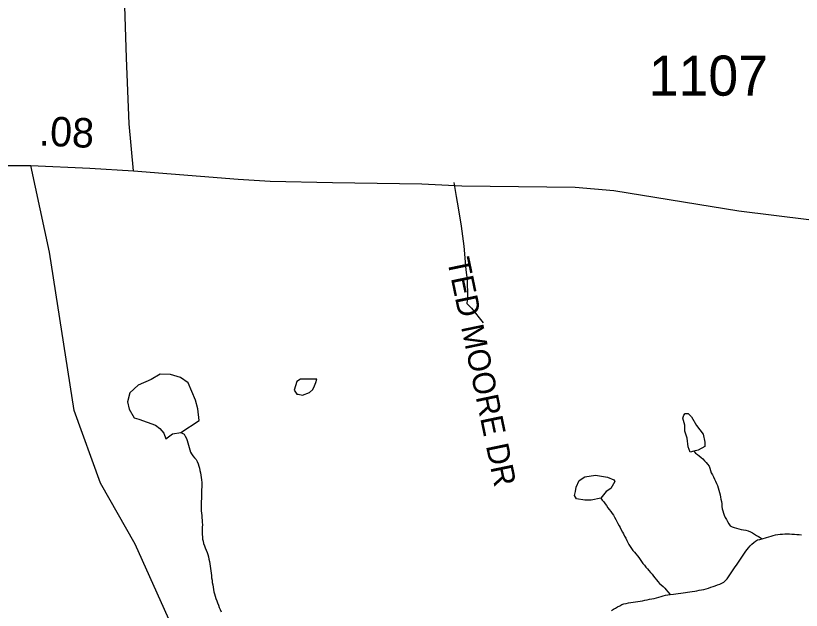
# Model space of a CAD drawing. Extents: x 1950930 to 2061844, y 904556 to 1017002.
# Drawn here: x 1975648 to 1978977, y 917429 to 919951 of the extents above; entities that cross this region are included whole.
import ezdxf

# ---------------------------------------------------------------- set-up
doc = ezdxf.new("R2010")
doc.units = 0
for name, color, linetype in [('Exist Hydrographic Creek Single Shore', 7, 'Continuous'), ('Exist Hydrographic Misc Water Feature', 7, 'Continuous'), ('Exist Road Non-System Type 51', 7, 'Continuous'), ('Exist Road Non-System Type 51 Label', 7, 'Continuous'), ('Exist Road Primary US Structure Standard Bridge CELL', 7, 'Continuous'), ('Exist Road Secondary Type 51 Attributed', 7, 'Continuous'), ('Exist Road Secondary Type 51 Number Label', 7, 'Continuous')]:
    doc.layers.add(name, color=color, linetype=linetype)

msp = doc.modelspace()

# ---------------------------------------------------------------- linework, layer by layer
at = {"layer": 'Exist Hydrographic Creek Single Shore'}
for points in [[(1978811.5, 917731.8), (1978830.3, 917737.1), (1978839.8, 917740.1), (1978849.2, 917743.1), (1978858.4, 917745.8), (1978868.3, 917748.7), (1978878.3, 917750.1), (1978888.3, 917751.3), (1978897.8, 917751.9), (1978908, 917752.8), (1978917.9, 917752.5), (1978927.7, 917753), (1978937.8, 917751.9), (1978947.8, 917752), (1978957.9, 917750.9), (1978967.9, 917749.8), (1978978, 917748.6)], [(1978421.4, 917495.2), (1978436.4, 917497.4), (1978445.8, 917498.8), (1978455.9, 917500.1), (1978466.4, 917501.8), (1978476, 917503.2), (1978486, 917504.5), (1978495.5, 917505.9), (1978505.5, 917507.6), (1978515.2, 917509), (1978525.6, 917510.3), (1978535.2, 917511.6), (1978544.9, 917514.2), (1978554.9, 917515.5), (1978564.6, 917517.7), (1978574.4, 917519.9), (1978583.8, 917522.9), (1978593.7, 917526.3), (1978603.1, 917529.3), (1978612.6, 917532.3), (1978622.2, 917536.2), (1978631.6, 917539.2), (1978640.9, 917544.3), (1978648.8, 917548.7), (1978656.2, 917555.3), (1978662.6, 917562.4), (1978668.7, 917571.3), (1978674.3, 917579.4), (1978680, 917588.2), (1978685.8, 917596.3), (1978691.3, 917604.8), (1978696.8, 917612.9), (1978702.4, 917620.5), (1978708.1, 917629.4), (1978713.8, 917637.9), (1978719.4, 917645.9), (1978725.1, 917654), (1978730.9, 917662.9), (1978736.4, 917670.9), (1978742.4, 917679), (1978748.3, 917687), (1978754.2, 917694.2), (1978761.2, 917702.5), (1978768.2, 917709.6), (1978776, 917717), (1978783.2, 917722.7), (1978791.6, 917727.1), (1978801.8, 917729.6), (1978811.5, 917731.8)], [(1978173.1, 917427.5), (1978181.7, 917433.1), (1978190.6, 917437.8), (1978198.6, 917443.1), (1978207.6, 917448.2), (1978216.4, 917453), (1978225.8, 917456), (1978235.7, 917458.2), (1978245.3, 917460.3), (1978255.4, 917461.7), (1978264.8, 917463.1), (1978275.2, 917464.7), (1978284.9, 917466.1), (1978294.9, 917467.4), (1978305, 917468.7), (1978314.6, 917471.3), (1978324.5, 917473.5), (1978333.7, 917475.7), (1978343.7, 917477.5), (1978353.4, 917479.6), (1978363.2, 917481.8), (1978373.5, 917484.7), (1978382.9, 917487.7), (1978392.1, 917490.4), (1978401.6, 917493.3), (1978411.6, 917494.7), (1978421.4, 917495.2)]]:
    msp.add_lwpolyline(points, dxfattribs=at)
at = {"layer": 'Exist Hydrographic Misc Water Feature'}
for points in [[(1976348.4, 918182.6), (1976426.3, 918233.7), (1976419.5, 918283.4), (1976409.5, 918319.5), (1976378.9, 918393.1), (1976346.7, 918416.7), (1976304.5, 918429.2), (1976260.6, 918430.9), (1976222.9, 918407.9), (1976166.9, 918383.6), (1976131.4, 918351.6), (1976121.6, 918313.3), (1976129.6, 918281.7), (1976150.3, 918245.3), (1976170.2, 918239.8), (1976240.3, 918214.1), (1976258.4, 918200.4), (1976276.6, 918180.2), (1976284.6, 918156.3), (1976312.7, 918177.1), (1976348.4, 918182.6)], [(1976845, 918344.9), (1976863.3, 918341.3), (1976893.2, 918353), (1976907.1, 918365.1), (1976914.9, 918381.4), (1976920.5, 918395.2), (1976924.6, 918409.5), (1976910.6, 918409.2), (1976896.7, 918409.3), (1976874.9, 918409), (1976854.4, 918408.8), (1976838.9, 918399.1), (1976828.8, 918362.5), (1976839.1, 918345), (1976845, 918344.9)], [(1978522.5, 918103.7), (1978507, 918099.2), (1978498.3, 918121.5), (1978494.2, 918159), (1978484, 918189.1), (1978483.8, 918213.4), (1978475.6, 918243.1), (1978479.3, 918257.2), (1978485.4, 918263.5), (1978497.3, 918263.3), (1978511.7, 918249.8), (1978533.6, 918213.2), (1978561.7, 918175.6), (1978568.5, 918142.1), (1978568.3, 918123.9), (1978540.6, 918107.4), (1978522.5, 918103.7)], [(1976348.4, 918182.6), (1976362.3, 918176.1), (1976367, 918166.8), (1976371.9, 918157.9), (1976375, 918148.6), (1976378.1, 918138.7), (1976380.8, 918129), (1976382.8, 918119), (1976385.7, 918110), (1976388.6, 918099.8), (1976393.3, 918091.8), (1976399.4, 918083.6), (1976406.4, 918076), (1976413.2, 918068.5), (1976417.1, 918059.4), (1976420.8, 918050.3), (1976423.6, 918040.1), (1976426.5, 918031.2), (1976428.5, 918021.2), (1976430.8, 918011.4), (1976432, 918001.5), (1976433.9, 917991.5), (1976435.7, 917981.9), (1976436.5, 917971.6), (1976436.5, 917961.9), (1976436.5, 917951.3), (1976435.7, 917941.7), (1976435.3, 917931.6), (1976435.5, 917921.9), (1976435.3, 917911.3), (1976434.9, 917901.2), (1976434.7, 917891.6), (1976434.3, 917881.8), (1976433.9, 917871.8), (1976434.3, 917861.2), (1976434.7, 917851.4), (1976435.3, 917841.5), (1976436.5, 917831.6), (1976437.4, 917821.7), (1976438.4, 917811.8), (1976438.8, 917802.1), (1976439.2, 917791.4), (1976438.8, 917781.3), (1976438.8, 917771.6), (1976438.6, 917761.9), (1976438.4, 917751), (1976439.2, 917741), (1976440.2, 917731.2), (1976442.1, 917721.6), (1976444.7, 917712.2), (1976447.8, 917702.5), (1976451.3, 917693.4), (1976455.4, 917684.2), (1976459.1, 917674.3), (1976462.8, 917665.3), (1976465.5, 917655.5), (1976467.3, 917646.3), (1976468.9, 917636.3), (1976471.2, 917626.6), (1976472.6, 917616.7), (1976473.9, 917606.7), (1976475.1, 917596.8), (1976476.5, 917586.9), (1976477.8, 917576.6), (1976478.6, 917566.2), (1976480.4, 917556.7), (1976481.2, 917546.8), (1976483.1, 917536.8), (1976484.7, 917526.8), (1976486.6, 917517.1), (1976488.2, 917507.2), (1976491.1, 917498.3), (1976493.5, 917488.1), (1976496.8, 917479.1), (1976499.9, 917469.3), (1976503.4, 917460.2), (1976507.5, 917451.1), (1976510.8, 917441.3), (1976514.5, 917432.1), (1976518.4, 917423)], [(1978522.5, 918103.7), (1978528.7, 918095.4), (1978536.9, 918090.2), (1978545.1, 918084.4), (1978552.9, 918077.5), (1978559.9, 918070.8), (1978567.2, 918063.2), (1978574, 918056.4), (1978580.4, 918048.2), (1978586.3, 918040.7), (1978590, 918031.7), (1978592, 918021.7), (1978595.9, 918011.7), (1978600.5, 918003.3), (1978605, 917994.5), (1978609.9, 917985.3), (1978614.2, 917976), (1978618.3, 917966.9), (1978621.8, 917957.9), (1978625.5, 917948.8), (1978628.1, 917939), (1978630.6, 917928.9), (1978632.9, 917919.2), (1978634.5, 917909.3), (1978636.3, 917900.1), (1978638.6, 917890.3), (1978640, 917880.4), (1978641.1, 917869.7), (1978642.5, 917859.8), (1978644.3, 917850.1), (1978647, 917841.2), (1978650.1, 917831.8), (1978655, 917822.6), (1978659.9, 917813.6), (1978664.8, 917805.2), (1978669.6, 917796), (1978675.3, 917787), (1978684.1, 917782.8), (1978692.7, 917779.5), (1978703, 917776.7), (1978712, 917774.9), (1978722.3, 917772.1), (1978732.1, 917770.3), (1978741.9, 917768.3), (1978751.8, 917765.7), (1978761.4, 917762.2), (1978770.2, 917757.1), (1978778.9, 917752.2), (1978787.3, 917746.8), (1978795.9, 917741.9), (1978811.5, 917731.8)], [(1978128, 917904.3), (1978086.4, 917896.1), (1978060.3, 917895.6), (1978024.3, 917901.4), (1978016.5, 917915.5), (1978020, 917933.3), (1978023.6, 917951.4), (1978035.7, 917980), (1978059.3, 917994.3), (1978105.3, 918002.3), (1978155.5, 917993.1), (1978183.2, 917982.8), (1978187.5, 917975.2), (1978169.6, 917945.1), (1978150.2, 917932.2), (1978128, 917904.3)], [(1978128, 917904.3), (1978134, 917896.5), (1978140.3, 917888.3), (1978146.1, 917880.1), (1978151.6, 917872.7), (1978158, 917864.1), (1978163.7, 917855.9), (1978169.6, 917848.5), (1978175.6, 917839.9), (1978180.9, 917831.7), (1978185.8, 917823.3), (1978190.8, 917814.4), (1978195.7, 917805.1), (1978200.2, 917796.7), (1978205.5, 917787.8), (1978210, 917779.4), (1978214.5, 917770.2), (1978219.3, 917760.9), (1978224, 917752.9), (1978228.3, 917743.7), (1978233.2, 917734.5), (1978237.5, 917725.3), (1978242, 917716.5), (1978246.5, 917708.1), (1978252.1, 917699.5), (1978257.4, 917691.4), (1978263.8, 917683.2), (1978270.1, 917675.7), (1978276.5, 917667.8), (1978282.8, 917659.6), (1978289.2, 917652.2), (1978294.5, 917644), (1978300.5, 917635.4), (1978306.4, 917628), (1978312.6, 917619.8), (1978318.7, 917612.4), (1978325.5, 917604.8), (1978331.8, 917597.3), (1978338.6, 917589.8), (1978345, 917581.9), (1978351.3, 917573.7), (1978357.3, 917566.2), (1978363.2, 917558), (1978369.6, 917550.7), (1978376.3, 917543.1), (1978383.7, 917536.3), (1978391.7, 917530.3), (1978398.9, 917523), (1978405.2, 917515.2), (1978411.6, 917507.7), (1978421.4, 917495.2)]]:
    msp.add_lwpolyline(points, dxfattribs=at)
at = {"layer": 'Exist Road Non-System Type 51'}
msp.add_lwpolyline([(1977504.5, 919243.4), (1977514.5, 919184.1), (1977523.8, 919135.3), (1977535.8, 919058.3), (1977547, 918973.5), (1977556.2, 918872.4), (1977560.8, 918830.3), (1977562.2, 918758.9), (1977560.2, 918730.1), (1977579.9, 918710.1), (1977628.6, 918647.9)], dxfattribs=at)
at = {"layer": 'Exist Road Secondary Type 51 Attributed'}
for points in [[(1976146.7, 919292.8), (1976128.7, 919492.2), (1976118.3, 919772.2), (1976109.8, 920036.1), (1976095.6, 920162.2), (1976085.3, 920310), (1976075.3, 920410), (1976071.1, 920512.2), (1976064.8, 920696.2), (1976074.6, 920888.1), (1976086.3, 921064), (1976103.9, 921400.2), (1976114.2, 921634.2), (1976126.7, 921748.2), (1976130.8, 921849.7), (1976130.8, 922022), (1976124.7, 922146), (1976114.2, 922220.4), (1976085.2, 922321.9), (1976050.3, 922420), (1976008.1, 922498), (1975974.1, 922545.8), (1975918.3, 922602.7)], [(1972525.2, 918328.2), (1972599.6, 918355.6), (1972670.9, 918389), (1972779.5, 918439.9), (1973078.6, 918604), (1973263.8, 918698.2), (1973346.6, 918741.6), (1973454.4, 918799.3), (1973560.6, 918835.8), (1973648.7, 918870.7), (1973844.6, 918946.7), (1973963.7, 918987), (1974142.9, 919040.2), (1974387.3, 919110.1), (1974599.9, 919172.4), (1974836, 919233.9), (1974977.2, 919262.8), (1975126, 919276.4), (1975239.1, 919289.4), (1975374.2, 919301.5), (1975574.6, 919315.2), (1975712, 919316)], [(1975712, 919316), (1975962.6, 919303.8), (1976146.7, 919292.8)], [(1976403.6, 917155.6), (1976154.8, 917709.2), (1976007.8, 917967.7), (1975895.7, 918276.3), (1975791.4, 918947.9), (1975712, 919316)], [(1976146.7, 919292.8), (1976590.8, 919256.9), (1976726.9, 919249.1), (1976991, 919243.4), (1977368.9, 919237.9), (1977539, 919229.1), (1978019.1, 919223.8), (1978182.9, 919209.1), (1978713, 919123.7), (1979009, 919086.1), (1979324.9, 919038.6), (1979707, 918979), (1979867.1, 918949.2), (1979967, 918937.5), (1980227, 918919.7), (1980567.2, 918886.3), (1980805.1, 918828.6), (1981143.2, 918737), (1981234.5, 918713.2)]]:
    msp.add_lwpolyline(points, dxfattribs=at)

# ---------------------------------------------------------------- texts
at = {"layer": 'Exist Road Non-System Type 51 Label'}
msp.add_text('  TED MOORE DR', height=95, rotation=281.7882, dxfattribs=at).set_placement((1977461.6, 918983.7))
at = {"layer": 'Exist Road Primary US Structure Standard Bridge CELL'}
msp.add_text('.08', height=125, rotation=357.2217, dxfattribs=at).set_placement((1975745.1, 919400.8))
at = {"layer": 'Exist Road Secondary Type 51 Number Label'}
msp.add_text('1107', height=170, dxfattribs=at).set_placement((1978330.7, 919611.7))

doc.saveas('drawing.dxf')
